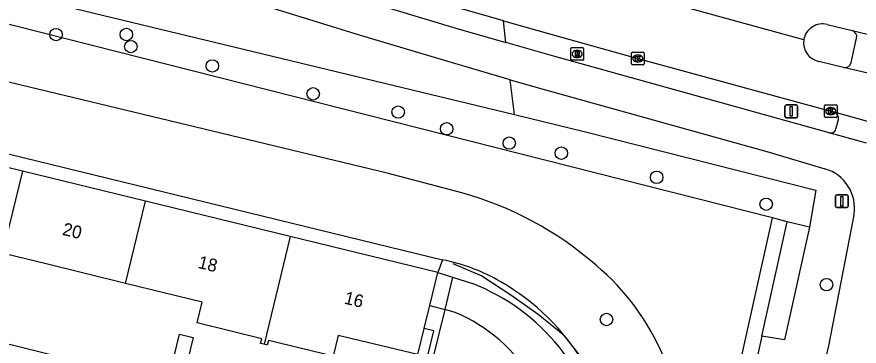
# Model space of a CAD drawing. Extents: x 163268 to 164360, y 381529 to 382285.
# Drawn here: x 164107.1 to 164173.3, y 382172.9 to 382198.8 of the extents above; entities that cross this region are included whole.
import ezdxf

# ---------------------------------------------------------------- set-up
doc = ezdxf.new("R2010")
doc.units = 0
for name, color, linetype in [('IMGEO_Berm_groen', 7, 'Continuous'), ('IMGEO_Boom', 7, 'Continuous'), ('IMGEO_Fietspad_gesloten', 7, 'Continuous'), ('IMGEO_Gemengd_bos', 7, 'Continuous'), ('IMGEO_Groenvoorziening', 7, 'Continuous'), ('IMGEO_Haag', 7, 'Continuous'), ('IMGEO_Kolk', 7, 'Continuous'), ('IMGEO_Loofbos', 7, 'Continuous'), ('IMGEO_Muur', 7, 'Continuous'), ('IMGEO_Pand', 7, 'Continuous'), ('IMGEO_Pand_nummerreeks', 7, 'Continuous'), ('IMGEO_Rijbaan_regionaal_gesloten', 7, 'Continuous'), ('IMGEO_Rioolput', 7, 'Continuous'), ('IMGEO_Verkeersbordpaal', 7, 'Continuous'), ('IMGEO_Voetpad_halfverhard', 7, 'Continuous'), ('IMGEO_Voetpad_open', 7, 'Continuous'), ('IMGEO_Waterloop', 7, 'Continuous')]:
    doc.layers.add(name, color=color, linetype=linetype)

msp = doc.modelspace()

# ---------------------------------------------------------------- linework, layer by layer
at = {"layer": 'IMGEO_Berm_groen'}
for points in [[(164145.581, 382196.793), (164145.381, 382198.501)], [(164146.245, 382191.123), (164145.924, 382193.866)], [(164169.438, 382182.271), (164167.471, 382173.44), (164165.692, 382173.731)]]:
    msp.add_lwpolyline(points, dxfattribs=at)
at = {"layer": 'IMGEO_Boom'}
for centre in [(164110.216, 382197.409), (164115.741, 382197.419), (164116.09, 382196.466), (164122.503, 382194.948), (164130.423, 382192.759), (164137.105, 382191.322), (164140.922, 382190.011), (164145.84, 382188.886), (164149.937, 382188.092), (164157.424, 382186.192), (164166.03, 382184.083), (164170.774, 382177.762), (164153.483, 382175.033)]:
    msp.add_circle(centre, 0.489, dxfattribs=at)
at = {"layer": 'IMGEO_Fietspad_gesloten'}
for points in [[(164114.687, 382206.165), (164121.575, 382204.092), (164128.496, 382201.936), (164134.841, 382199.95), (164141.648, 382197.918), (164145.581, 382196.793)], [(164145.924, 382193.866), (164140.941, 382195.309), (164134.075, 382197.359), (164127.632, 382199.361), (164120.905, 382201.457), (164113.934, 382203.558)], [(164170.978, 382189.695), (164149.41, 382195.697), (164145.581, 382196.793)], [(164145.924, 382193.866), (164148.695, 382193.064), (164166.276, 382188.165), (164170.648, 382186.869)], [(164173.926, 382188.877), (164170.978, 382189.695)], [(164172.93, 382183.227), (164172.562, 382181.332), (164170.934, 382172.953), (164169.489, 382166.782)]]:
    msp.add_lwpolyline(points, dxfattribs=at)
msp.add_arc((164169.774, 382183.785), 3.205, 349.96735, 74.17342, dxfattribs=at)
at = {"layer": 'IMGEO_Gemengd_bos'}
for points in [[(164140.582, 382179.712), (164140.224, 382178.727)], [(164140.224, 382178.727), (164141.384, 382178.355)], [(164141.384, 382178.355), (164142.946, 382177.855)]]:
    msp.add_lwpolyline(points, dxfattribs=at)
msp.add_arc((164136.892, 382162.451), 16.551, 9.49332, 68.54379, dxfattribs=at)
at = {"layer": 'IMGEO_Groenvoorziening'}
for points in [[(164141.384, 382178.355), (164140.763, 382175.807)], [(164139.594, 382176.121), (164140.763, 382175.807)], [(164140.763, 382175.807), (164139.83, 382171.985)], [(164141.596, 382175.584), (164140.763, 382175.807)]]:
    msp.add_lwpolyline(points, dxfattribs=at)
msp.add_arc((164136.441, 382163.448), 13.186, 355.83029, 66.98742, dxfattribs=at)
at = {"layer": 'IMGEO_Haag'}
for points in [[(164163.229, 382168.198), (164166.532, 382183.008)], [(164165.692, 382173.731), (164167.695, 382182.713)], [(164165.692, 382173.731), (164164.399, 382167.933)]]:
    msp.add_lwpolyline(points, dxfattribs=at)
at = {"layer": 'IMGEO_Kolk'}
for p, q in [((164155.448, 382195.101), (164155.448, 382195.953)), ((164155.523, 382196.027), (164156.375, 382196.027)), ((164155.936, 382195.807), (164155.961, 382195.807)), ((164156.449, 382195.953), (164156.449, 382195.101)), ((164156.375, 382195.027), (164155.523, 382195.027)), ((164155.959, 382195.247), (164155.934, 382195.247)), ((164170.612, 382190.973), (164170.612, 382191.825)), ((164170.687, 382191.899), (164171.539, 382191.899)), ((164171.1, 382191.679), (164171.125, 382191.679)), ((164171.613, 382191.825), (164171.613, 382190.973)), ((164171.123, 382191.119), (164171.098, 382191.119)), ((164171.539, 382190.899), (164170.687, 382190.899))]:
    msp.add_line(p, q, dxfattribs=at)
for points in [[(164155.448, 382195.101), (164155.448, 382195.953)], [(164155.523, 382196.027), (164156.375, 382196.027)], [(164155.769, 382195.727), (164155.892, 382195.727), (164155.892, 382195.576), (164156.022, 382195.727), (164156.186, 382195.727), (164156.04, 382195.576), (164156.193, 382195.327), (164156.041, 382195.327), (164155.956, 382195.491), (164155.892, 382195.424), (164155.892, 382195.327), (164155.769, 382195.327), (164155.769, 382195.727)], [(164156.449, 382195.953), (164156.449, 382195.101)], [(164156.375, 382195.027), (164155.523, 382195.027)], [(164170.612, 382190.973), (164170.612, 382191.825)], [(164170.687, 382191.899), (164171.539, 382191.899)], [(164170.933, 382191.599), (164171.056, 382191.599), (164171.056, 382191.448), (164171.186, 382191.599), (164171.35, 382191.599), (164171.204, 382191.448), (164171.357, 382191.199), (164171.205, 382191.199), (164171.12, 382191.363), (164171.056, 382191.296), (164171.056, 382191.199), (164170.933, 382191.199), (164170.933, 382191.599)], [(164171.613, 382191.825), (164171.613, 382190.973)], [(164171.539, 382190.899), (164170.687, 382190.899)]]:
    msp.add_lwpolyline(points, dxfattribs=at)
for centre, start, end in [((164155.525, 382195.951), 91.55205, 178.44795), ((164155.525, 382195.951), 91.55205, 178.44795), ((164156.373, 382195.951), 1.55205, 88.44795), ((164156.373, 382195.951), 1.55205, 88.44795), ((164155.525, 382195.103), 181.55205, 268.44795), ((164155.525, 382195.103), 181.55205, 268.44795), ((164156.373, 382195.103), 271.55205, 358.44795), ((164156.373, 382195.103), 271.55205, 358.44795), ((164170.689, 382191.823), 91.55205, 178.44795), ((164170.689, 382191.823), 91.55205, 178.44795), ((164171.537, 382191.823), 1.55205, 88.44795), ((164171.537, 382191.823), 1.55205, 88.44795), ((164170.689, 382190.975), 181.55205, 268.44795), ((164170.689, 382190.975), 181.55205, 268.44795), ((164171.537, 382190.975), 271.55205, 358.44795), ((164171.537, 382190.975), 271.55205, 358.44795)]:
    msp.add_arc(centre, 0.0765, start, end, dxfattribs=at)
for centre, major_axis, ratio, start_param, end_param in [((164155.935, 382195.527), (-0.387, 0.002), 0.722429, 4.712389, 7.853982), ((164155.96, 382195.527), (-0.39, 0.002), 0.717154, 1.570796, 4.712389), ((164171.099, 382191.399), (-0.387, 0.002), 0.722429, 4.712389, 7.853982), ((164171.124, 382191.399), (-0.39, 0.002), 0.717154, 1.570796, 4.712389)]:
    msp.add_ellipse(centre, major_axis=major_axis, ratio=ratio, start_param=start_param, end_param=end_param, dxfattribs=at)
at = {"layer": 'IMGEO_Loofbos'}
for points in [[(164142.104, 382184.986), (164136.238, 382186.518), (164000, 382219.278), (163872.239, 382250), (163832.907, 382259.458), (163823.874, 382261.74)], [(163819.962, 382253.749), (163820.909, 382257.71), (163830.652, 382255.331), (163852.505, 382250), (164000, 382214.018), (164033.312, 382205.891), (164134.264, 382181.264), (164140.582, 382179.712)]]:
    msp.add_lwpolyline(points, dxfattribs=at)
for centre, radius, start, end in [((164134.735, 382158.675), 27.323, 48.97971, 74.35411), ((164137.929, 382165.692), 14.268, 59.52837, 79.28557), ((164140.344, 382164.665), 19.125, 356.03507, 49.87905), ((164136.036, 382162.116), 18.312, 2.09183, 60.09797)]:
    msp.add_arc(centre, radius, start, end, dxfattribs=at)
at = {"layer": 'IMGEO_Muur'}
msp.add_lwpolyline([(164141.417, 382179.428), (164143.675, 382178.448), (164145.975, 382176.975), (164148.108, 382175.447), (164150.041, 382173.88), (164151.674, 382171.806), (164153.122, 382169.652)], dxfattribs=at)
at = {"layer": 'IMGEO_Pand'}
for points in [[(164107.574, 382186.69), (164097.92, 382189.045)], [(164107.574, 382186.69), (164105.933, 382179.916)], [(164117.248, 382184.331), (164107.574, 382186.69)], [(164115.682, 382177.868), (164117.248, 382184.331)], [(164128.622, 382181.557), (164117.248, 382184.331)], [(164128.622, 382181.557), (164126.564, 382173.084)], [(164140.224, 382178.727), (164128.622, 382181.557)], [(164115.682, 382177.868), (164109.43, 382179.394), (164106.184, 382180.187), (164106.107, 382179.874), (164105.933, 382179.916)], [(164139.594, 382176.121), (164140.224, 382178.727)], [(164126.564, 382173.084), (164126.293, 382173.155), (164126.384, 382173.523), (164121.311, 382174.762), (164121.71, 382176.396), (164115.682, 382177.868)], [(164139.159, 382174.319), (164139.594, 382176.121)], [(164119.029, 382170.199), (164119.926, 382173.874), (164120.999, 382173.613), (164120.101, 382169.937), (164119.029, 382170.199)], [(164138.663, 382172.267), (164132.391, 382173.784), (164131.994, 382172.155), (164126.908, 382173.385), (164126.817, 382173.017), (164126.564, 382173.084)], [(164138.663, 382172.267), (164139.159, 382174.319)]]:
    msp.add_lwpolyline(points, dxfattribs=at)
at = {"layer": 'IMGEO_Rijbaan_regionaal_gesloten'}
for points in [[(164168.992, 382196.989), (164110.727, 382212.993), (164108.063, 382213.649), (164084.317, 382219.681), (164050.881, 382227.901), (164039.616, 382230.67), (164039.572, 382230.68), (164037.966, 382231.039), (164021.357, 382234.757), (164000.218, 382240.119), (163959.257, 382250.019), (163946.662, 382253.077), (163934.94, 382255.953), (163882.94, 382268.712), (163831.273, 382281.773), (163817.646, 382284.779)], [(164145.381, 382198.501), (164142.019, 382199.457), (164135.615, 382201.432), (164129.199, 382203.466)], [(164145.381, 382198.501), (164149.939, 382197.205), (164155.945, 382195.528), (164171.11, 382191.4), (164171.34, 382191.331)], [(164170.835, 382198.2), (164172.789, 382197.731)], [(164172.789, 382197.731), (164175.847, 382196.99)], [(164172.125, 382194.829), (164170.175, 382195.308)], [(164175.16, 382194.107), (164172.125, 382194.829)], [(164171.34, 382191.331), (164174.36, 382190.503)]]:
    msp.add_lwpolyline(points, dxfattribs=at)
for centre, start, end in [((164170.458, 382196.765), 75.29617, 171.32013), ((164170.457, 382196.763), 171.24746, 259.02431)]:
    msp.add_arc(centre, 1.483, start, end, dxfattribs=at)
at = {"layer": 'IMGEO_Rioolput'}
for p, q in [((164150.678, 382195.462), (164150.678, 382196.314)), ((164150.753, 382196.388), (164151.605, 382196.388)), ((164151.679, 382196.314), (164151.679, 382195.462)), ((164151.189, 382195.608), (164151.164, 382195.608)), ((164151.166, 382196.168), (164151.191, 382196.168)), ((164151.605, 382195.388), (164150.753, 382195.388))]:
    msp.add_line(p, q, dxfattribs=at)
for points in [[(164150.678, 382195.462), (164150.678, 382196.314)], [(164150.753, 382196.388), (164151.605, 382196.388)], [(164151.679, 382196.314), (164151.679, 382195.462)], [(164151.267, 382196.086), (164151.015, 382196.088), (164151.015, 382195.688)], [(164151.015, 382195.688), (164151.139, 382195.688), (164151.139, 382195.85), (164151.15, 382195.85)], [(164151.193, 382196.007), (164151.139, 382196.007), (164151.139, 382195.926)], [(164151.139, 382195.926), (164151.191, 382195.926)], [(164151.197, 382195.821), (164151.268, 382195.688), (164151.408, 382195.688), (164151.343, 382195.814)], [(164151.605, 382195.388), (164150.753, 382195.388)]]:
    msp.add_lwpolyline(points, dxfattribs=at)
for centre, radius, start, end in [((164150.755, 382196.312), 0.0765, 91.55205, 178.44795), ((164150.755, 382196.312), 0.0765, 91.55205, 178.44795), ((164151.603, 382196.312), 0.0765, 1.55205, 88.44795), ((164151.603, 382196.312), 0.0765, 1.55205, 88.44795), ((164151.149, 382195.797), 0.0533, 26.02933, 88.69889), ((164151.175, 382196.115), 0.19, 274.7715, 282.96867), ((164151.199, 382195.911), 0.0964, 77.00612, 93.18647), ((164151.213, 382195.968), 0.0378, 276.66336, 79.67722), ((164151.266, 382195.976), 0.109, 350.36119, 89.41601), ((164151.264, 382195.976), 0.112, 277.58423, 350.98172), ((164151.248, 382195.761), 0.108, 29.51342, 73.79051), ((164150.755, 382195.464), 0.0765, 181.55205, 268.44795), ((164150.755, 382195.464), 0.0765, 181.55205, 268.44795), ((164151.603, 382195.464), 0.0765, 271.55205, 358.44795), ((164151.603, 382195.464), 0.0765, 271.55205, 358.44795)]:
    msp.add_arc(centre, radius, start, end, dxfattribs=at)
for centre, major_axis, ratio, start_param, end_param in [((164151.165, 382195.888), (-0.387, 0.002), 0.722429, 4.712389, 7.853982), ((164151.19, 382195.888), (-0.39, 0.002), 0.717154, 1.570796, 4.712389)]:
    msp.add_ellipse(centre, major_axis=major_axis, ratio=ratio, start_param=start_param, end_param=end_param, dxfattribs=at)
at = {"layer": 'IMGEO_Verkeersbordpaal'}
for p, q in [((164167.512, 382190.98), (164167.512, 382191.78)), ((164167.512, 382191.78), (164167.512, 382190.98)), ((164167.612, 382191.88), (164168.402, 382191.88)), ((164168.402, 382191.88), (164167.612, 382191.88)), ((164168.502, 382191.78), (164168.502, 382190.98)), ((164168.502, 382190.98), (164168.502, 382191.78)), ((164168.402, 382190.88), (164167.612, 382190.88)), ((164167.612, 382190.88), (164168.402, 382190.88)), ((164171.488, 382183.918), (164171.488, 382184.718)), ((164171.488, 382184.718), (164171.488, 382183.918)), ((164171.588, 382184.818), (164172.378, 382184.818)), ((164172.378, 382184.818), (164171.588, 382184.818)), ((164172.478, 382184.718), (164172.478, 382183.918)), ((164172.478, 382183.918), (164172.478, 382184.718)), ((164172.378, 382183.818), (164171.588, 382183.818)), ((164171.588, 382183.818), (164172.378, 382183.818))]:
    msp.add_line(p, q, dxfattribs=at)
for points in [[(164167.932, 382191.755), (164168.082, 382191.755), (164168.082, 382191.005), (164167.932, 382191.005), (164167.932, 382191.755)], [(164171.908, 382184.693), (164172.058, 382184.693), (164172.058, 382183.943), (164171.908, 382183.943), (164171.908, 382184.693)]]:
    msp.add_lwpolyline(points, dxfattribs=at)
for centre, start, end in [((164167.612, 382191.78), 90, 180), ((164167.612, 382191.78), 90, 180), ((164168.402, 382191.78), 0, 90), ((164168.402, 382191.78), 360, 90), ((164167.612, 382190.98), 180, 270), ((164167.612, 382190.98), 180, 270), ((164168.402, 382190.98), 270, 0), ((164168.402, 382190.98), 270, 0), ((164171.588, 382184.718), 90, 180), ((164171.588, 382184.718), 90, 180), ((164172.378, 382184.718), 0, 90), ((164172.378, 382184.718), 360, 90), ((164171.588, 382183.918), 180, 270), ((164171.588, 382183.918), 180, 270), ((164172.378, 382183.918), 270, 0), ((164172.378, 382183.918), 270, 0)]:
    msp.add_arc(centre, 0.1, start, end, dxfattribs=at)
at = {"layer": 'IMGEO_Voetpad_halfverhard'}
msp.add_lwpolyline([(164139.401, 382172.089), (164139.9, 382174.138), (164139.159, 382174.319)], dxfattribs=at)
at = {"layer": 'IMGEO_Voetpad_open'}
for points in [[(164172.722, 382195.227), (164173.146, 382197.131)], [(164171.543, 382190.088), (164171.712, 382190.731)], [(164100.999, 382174.463), (164107.813, 382172.789), (164120.079, 382169.717), (164129.099, 382167.519)]]:
    msp.add_lwpolyline(points, dxfattribs=at)
for centre, radius, start, end in [((164172.651, 382197.242), 0.508, 347.32941, 74.17588), ((164172.214, 382195.343), 0.521, 260.1942, 347.18593), ((164171.192, 382190.824), 0.529, 349.89666, 73.70117), ((164171.077, 382190.156), 0.471, 257.88893, 351.75411)]:
    msp.add_arc(centre, radius, start, end, dxfattribs=at)
at = {"layer": 'IMGEO_Waterloop'}
for points in [[(164061.215, 382209.546), (164061.732, 382211.747), (164086.771, 382205.491), (164146.245, 382191.123)], [(164166.532, 382183.008), (164097.094, 382200.621), (164061.215, 382209.546)], [(164146.245, 382191.123), (164151.833, 382189.773), (164169.934, 382185.191), (164169.438, 382182.271)], [(164167.695, 382182.713), (164166.532, 382183.008)], [(164169.438, 382182.271), (164167.695, 382182.713)]]:
    msp.add_lwpolyline(points, dxfattribs=at)

# ---------------------------------------------------------------- texts
at = {"layer": 'IMGEO_Pand_nummerreeks'}
for s, rotation, p in [('20', 346.2853, (164110.652, 382181.689)), ('18', 346.30306, (164121.312, 382179.09)), ('16', 346.30306, (164132.799, 382176.29))]:
    msp.add_text(s, height=1, rotation=rotation, dxfattribs=at).set_placement(p)

doc.saveas('drawing.dxf')
